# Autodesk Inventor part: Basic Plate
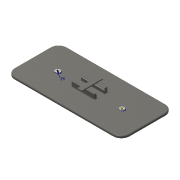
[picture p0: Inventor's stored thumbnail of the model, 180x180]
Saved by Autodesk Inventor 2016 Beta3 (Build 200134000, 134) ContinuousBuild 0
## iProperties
Created: 2016-02
Part Number: Basic Plate
Material: Steel, Cast
Document SubType Name: Modeling
Designer: User
Density: 7.85 g/cm^3
Appearance: Steel - Cast
Author: User
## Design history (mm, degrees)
sketch "Sketch1"
  geometry: L1 (-275, -125)-(275, -125); L2 (275, -125)-(275, 125); L3 (275, 125)-(-275, 125); L4 (-275, 125)-(-275, -125); L5 (-275, -125)-(275, 125); L6 (275, -125)-(-275, 125); 1 further point
  constraints: 12 end point, 2 midpoint, 2 parallel, 1 horizontal, 1 perpendicular
  dimensions: "d0" = 550 distance of L3.end L2.end; "d1" = 250 distance of L2.end L1.end
extrude "Extrusion1" new body sketch "Sketch1" distance "d2" = 10; taper "d3" = 0 deg
fillet "Fillet1" dims "d4" = 40
fillet "Fillet2" dims "d5" = 5
sketch "Sketch2"
  geometry: C1 r 10 at (-235, 85); C2 r 10 at (-235, -85); C3 r 10 at (235, -85); C4 r 10 at (235, 85); A1 r 40 centre (-235, -85) between (-275, -85) and (-235, -125) reference; A2 r 40 centre (235, -85) between (235, -125) and (275, -85) reference; A3 r 40 centre (235, 85) between (275, 85) and (235, 125) reference; A4 r 40 centre (-235, 85) between (-235, 125) and (-275, 85) reference; 1 further point
  constraints: 4 centre point, 4 coincident, 3 equal radius
  dimensions: "d6" = 20 diameter of C1
extrude "Extrusion2" join sketch "Sketch2" distance "d7" = 16; taper "d8" = 0 deg
fillet "Fillet3" dims "d9" = 5
fillet "Fillet4" dims "d10" = 2
sketch "Sketch3"
  geometry: L1 (-270, -85)-(-270, 85) reference; L2 (-153.5, 0)-(153.5, 0); 4 further points
  constraints: 3 coincident, 2 end point, 1 midpoint, 1 perpendicular
  dimensions: "d11" = 307 distance of L2.start L2.end
hole "Hole1" sketch "Sketch3" at (-153.5, 0), (153.5, 0) diameter "d12" = 12; stored, may be unused: countersink angle "d16" = 90 deg, drill point angle "d18" = 118 deg; dims "d13" = 6, "d14" = 4, "d15" = 2, "d17" = 8
sketch "Sketch4"
  geometry: C1 r 6 at (-153.5, 0) reference; C2 r 6 at (153.5, 0) reference; C3 r 12 at (-153.5, 0); C4 r 12 at (153.5, 0); 1 further point
  constraints: 2 centre point, 2 coincident, 1 equal radius
  dimensions: "d19" = 24 diameter of C3
extrude "Extrusion3" join sketch "Sketch4" distance "d20" = 4; taper "d21" = 0 deg
extrude "Extrusion7" join sketch "Sketch4" distance "d38" = 2; taper "d39" = 0 deg
fillet "Fillet5" dims "d22" = 2
sketch "Sketch5"
  geometry: L1 (50.5, -29.308)-(-61.5, -29.308); L2 (-61.5, -29.308)-(-61.5, 35.692); L3 (-61.5, 35.692)-(50.5, 35.692); L4 (50.5, 35.692)-(50.5, -29.308); L5 (50.5, -29.308)-(-61.5, 35.692); L6 (-61.5, -29.308)-(50.5, 35.692); C1 r 14 at (-153.5, 0) reference; 1 further point
  constraints: 12 end point, 2 parallel, 1 horizontal, 1 perpendicular, 1 point on line
  dimensions: "d23" = 112 distance of L2.end L3.end; "d24" = 65 distance of L1.end L2.end; "d33" = 92 distance from line of L2 C1.centre
extrude "Extrusion4" join sketch "Sketch5" distance "d25" = 24; taper "d26" = 0 deg
fillet "Fillet6" dims "d27" = 4
sketch "Sketch6"
  geometry: L1 (-61.5, 35.692)-(-61.5, -29.308) reference; L2 (61.5, -20)-(-61.5, -20); L3 (-61.5, -20)-(-61.5, 20); L4 (-61.5, 20)-(61.5, 20); L5 (61.5, 20)-(61.5, -20); L6 (61.5, -20)-(-61.5, 20); L7 (-61.5, -20)-(61.5, 20); 1 further point
  constraints: 12 end point, 2 midpoint, 2 parallel, 1 horizontal, 1 perpendicular, 1 point on line
  dimensions: "d28" = 40 distance of L2.end L3.end
extrude "Extrusion5" cut sketch "Sketch6" distance "d29" = 8; taper "d30" = 0 deg
fillet "Fillet7" dims "d31" = 4
fillet "Fillet8" dims "d32" = 2
sketch "Sketch7"
  geometry: L1 (235, -120)-(-235, -120) reference; L2 (270, 85)-(270, -85) reference; L3 (-235, 120)-(235, 120) reference; L4 (-270, -85)-(-270, 85) reference; L5 (54.5, -33.308)-(54.5, 39.692) reference; L6 (-65.5, -33.308)-(54.5, -33.308) reference; L7 (-65.5, 39.692)-(-65.5, -33.308) reference; L8 (54.5, 39.692)-(-65.5, 39.692) reference; L9 (-65.5, 18)-(54.5, 18); L10 (54.5, 18)-(54.5, -18); L11 (54.5, -18)-(-65.5, -18); L12 (-65.5, -18)-(-65.5, 18); C1 r 14 at (-153.5, 0) reference; A1 r 35 centre (235, -85) between (235, -120) and (270, -85) reference; A2 r 35 centre (235, 85) between (270, 85) and (235, 120) reference; A3 r 35 centre (-235, 85) between (-235, 120) and (-270, 85) reference; A4 r 35 centre (-235, -85) between (-270, -85) and (-235, -120) reference; 2 further points
  constraints: 8 end point, 2 parallel, 2 point on line, 1 horizontal, 1 horizontal alignment, 1 midpoint, 1 perpendicular
  dimensions: "d34" = 36 distance between parallel lines of L11 L9
extrude "Extrusion6" cut sketch "Sketch7" stored distance "d35" = 12; taper "d36" = 0 deg
fillet "Fillet9" dims "d37" = 4
sketch "Sketch9"
  geometry: L1 (-10.595, -49.975)-(10.595, -49.975); L2 (10.595, -49.975)-(10.595, 49.975); L3 (10.595, 49.975)-(-10.595, 49.975); L4 (-10.595, 49.975)-(-10.595, -49.975); L5 (-10.595, -49.975)-(10.595, 49.975); L6 (10.595, -49.975)-(-10.595, 49.975); 1 further point
  constraints: 12 end point, 2 midpoint, 2 parallel, 1 horizontal, 1 perpendicular
extrude "Extrusion8" join sketch "Sketch9" distance "d40" = 5; taper "d41" = 0 deg
body "Solid1"
node "Projected Loop1"
